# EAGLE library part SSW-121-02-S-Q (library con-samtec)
THROUGH-HOLE .025" SQ POST SOCKET Source: Samtec SSW.pdf
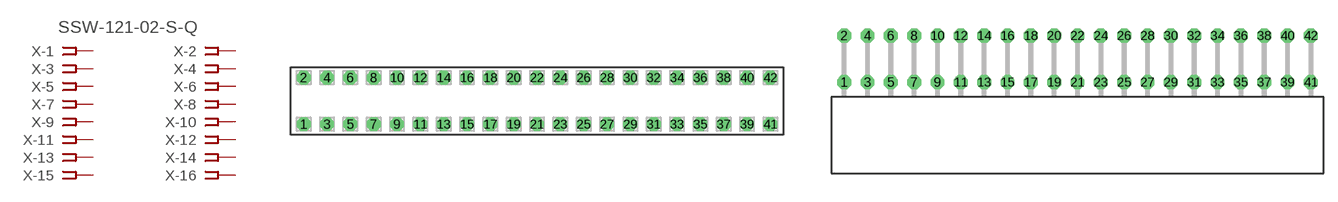
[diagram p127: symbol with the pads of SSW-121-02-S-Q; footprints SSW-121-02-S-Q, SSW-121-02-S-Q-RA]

Designator prefix X; gates -1=FPINV -2=FPIN -3=FPIN -4=FPIN -5=FPIN -6=FPIN -7=FPIN -8=FPIN -9=FPIN -10=FPIN -11=FPIN -12=FPIN -13=FPIN -14=FPIN -15=FPIN -16=FPIN -17=FPIN -18=FPIN -19=FPIN -20=FPIN -21=FPIN -22=FPIN -23=FPIN -24=FPIN -25=FPIN -26=FPIN -27=FPIN -28=FPIN -29=FPIN -30=FPIN -31=FPIN -32=FPIN -33=FPIN -34=FPIN -35=FPIN -36=FPIN -37=FPIN -38=FPIN -39=FPIN -40=FPIN -41=FPIN -42=FPIN

## SSW-121-02-S-Q (MPN: SSW-121-02-S-Q; OC_FARNELL: unknown; OC_NEWARK: 82P8644)  [SSW-121-02-S-Q]
1  -1:1  pas
2  -2:1  pas
3  -3:1  pas
4  -4:1  pas
5  -5:1  pas
6  -6:1  pas
7  -7:1  pas
8  -8:1  pas
9  -9:1  pas
10  -10:1  pas
11  -11:1  pas
12  -12:1  pas
13  -13:1  pas
14  -14:1  pas
15  -15:1  pas
16  -16:1  pas
17  -17:1  pas
18  -18:1  pas
19  -19:1  pas
20  -20:1  pas
21  -21:1  pas
22  -22:1  pas
23  -23:1  pas
24  -24:1  pas
25  -25:1  pas
26  -26:1  pas
27  -27:1  pas
28  -28:1  pas
29  -29:1  pas
30  -30:1  pas
31  -31:1  pas
32  -32:1  pas
33  -33:1  pas
34  -34:1  pas
35  -35:1  pas
36  -36:1  pas
37  -37:1  pas
38  -38:1  pas
39  -39:1  pas
40  -40:1  pas
41  -41:1  pas
42  -42:1  pas

## SSW-121-02-S-QRA (OC_FARNELL: unknown; OC_NEWARK: unknown)  [SSW-121-02-S-Q-RA]
Pads as for SSW-121-02-S-Q

## Footprint SSW-121-02-S-Q (pad centres in mm)
THROUGH-HOLE .025" SQ POST SOCKET Source: Samtec SSW.pdf
drill 1 pad 1.5 octagon: 1 -25.4,-2.54; 2 -25.4,2.54; 3 -22.86,-2.54; 4 -22.86,2.54; 5 -20.32,-2.54; 6 -20.32,2.54; 7 -17.78,-2.54; 8 -17.78,2.54; 9 -15.24,-2.54; 10 -15.24,2.54; 11 -12.7,-2.54; 12 -12.7,2.54; 13 -10.16,-2.54; 14 -10.16,2.54; 15 -7.62,-2.54; 16 -7.62,2.54; 17 -5.08,-2.54; 18 -5.08,2.54; 19 -2.54,-2.54; 20 -2.54,2.54; 21 0,-2.54; 22 0,2.54; 23 2.54,-2.54; 24 2.54,2.54; 25 5.08,-2.54; 26 5.08,2.54; 27 7.62,-2.54; 28 7.62,2.54; 29 10.16,-2.54; 30 10.16,2.54; 31 12.7,-2.54; 32 12.7,2.54; 33 15.24,-2.54; 34 15.24,2.54; 35 17.78,-2.54; 36 17.78,2.54; 37 20.32,-2.54; 38 20.32,2.54; 39 22.86,-2.54; 40 22.86,2.54; 41 25.4,-2.54; 42 25.4,2.54

## Footprint SSW-121-02-S-Q-RA (pad centres in mm)
THROUGH-HOLE .025" SQ POST SOCKET Source: Samtec SSW.pdf
drill 1 pad 1.5 octagon: 1 -25.4,1.524; 2 -25.4,6.604; 3 -22.86,1.524; 4 -22.86,6.604; 5 -20.32,1.524; 6 -20.32,6.604; 7 -17.78,1.524; 8 -17.78,6.604; 9 -15.24,1.524; 10 -15.24,6.604; 11 -12.7,1.524; 12 -12.7,6.604; 13 -10.16,1.524; 14 -10.16,6.604; 15 -7.62,1.524; 16 -7.62,6.604; 17 -5.08,1.524; 18 -5.08,6.604; 19 -2.54,1.524; 20 -2.54,6.604; 21 0,1.524; 22 0,6.604; 23 2.54,1.524; 24 2.54,6.604; 25 5.08,1.524; 26 5.08,6.604; 27 7.62,1.524; 28 7.62,6.604; 29 10.16,1.524; 30 10.16,6.604; 31 12.7,1.524; 32 12.7,6.604; 33 15.24,1.524; 34 15.24,6.604; 35 17.78,1.524; 36 17.78,6.604; 37 20.32,1.524; 38 20.32,6.604; 39 22.86,1.524; 40 22.86,6.604; 41 25.4,1.524; 42 25.4,6.604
